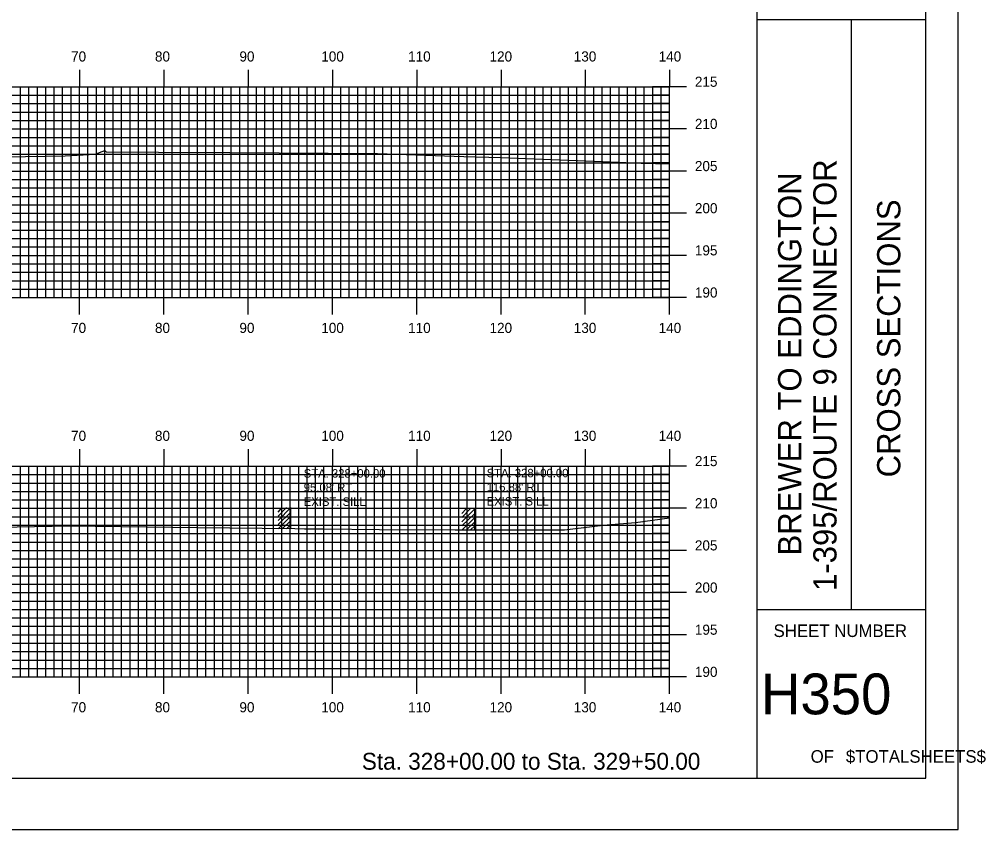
# Model space of a CAD drawing. Extents: x 1821998 to 1822342, y 442591 to 442811.
# Drawn here: x 1822227.1 to 1822341.8, y 442590.5 to 442686.7 of the extents above; entities that cross this region are included whole.
import ezdxf

# ---------------------------------------------------------------- set-up
doc = ezdxf.new("R2010")
doc.units = 0
for name, color, linetype in [('BORDER', 7, 'Continuous'), ('D_Text_Monospaced', 7, 'Continuous'), ('H_V ANNOTATION', 7, 'Continuous'), ('M_Buildings_Attachments', 7, 'Continuous'), ('MAJOR', 7, 'Continuous'), ('MINOR', 7, 'Continuous'), ('PLOT BOUNDARY', 7, 'Continuous'), ('S_Roadway_Centerline', 7, 'Continuous')]:
    doc.layers.add(name, color=color, linetype=linetype)

msp = doc.modelspace()

# ---------------------------------------------------------------- linework, layer by layer
at = {"layer": 'BORDER'}
for p, q in [((1822314.66, 442596.67), (1822314.66, 442806.67)), ((1822314.66, 442686.67), (1822334.66, 442686.67)), ((1822325.84, 442616.67), (1822325.84, 442686.67)), ((1822314.66, 442616.67), (1822334.66, 442616.67))]:
    msp.add_line(p, q, dxfattribs=at)
msp.add_lwpolyline([(1822014.66, 442596.67), (1822334.66, 442596.67), (1822334.66, 442806.67), (1822014.66, 442806.67)], close=True, dxfattribs=at)
at = {"layer": 'M_Buildings_Attachments'}
for p, q in [((1822257.83, 442627.24), (1822259.34, 442628.75)), ((1822257.83, 442627.73), (1822258.81, 442628.75)), ((1822257.83, 442628.23), (1822258.32, 442628.75)), ((1822259.34, 442626.23), (1822259.34, 442628.75)), ((1822279.63, 442627.08), (1822281.14, 442628.59)), ((1822279.63, 442627.57), (1822280.61, 442628.59)), ((1822279.63, 442628.06), (1822280.12, 442628.59)), ((1822281.14, 442626.06), (1822281.14, 442628.59)), ((1822257.83, 442626.75), (1822259.34, 442628.23)), ((1822257.83, 442626.23), (1822259.34, 442627.73)), ((1822258.32, 442626.23), (1822259.34, 442627.24)), ((1822279.63, 442626.59), (1822281.14, 442628.06)), ((1822279.63, 442626.06), (1822281.14, 442627.57)), ((1822258.81, 442626.23), (1822259.34, 442626.75)), ((1822280.12, 442626.06), (1822281.14, 442627.08)), ((1822280.61, 442626.06), (1822281.14, 442626.59))]:
    msp.add_line(p, q, dxfattribs=at)
at = {"layer": 'MAJOR'}
for p, q in [((1822234.26, 442680.67), (1822234.26, 442678.67)), ((1822244.26, 442680.67), (1822244.26, 442678.67)), ((1822254.26, 442680.67), (1822254.26, 442678.67)), ((1822264.26, 442680.67), (1822264.26, 442678.67)), ((1822274.26, 442680.67), (1822274.26, 442678.67)), ((1822284.26, 442680.67), (1822284.26, 442678.67)), ((1822294.26, 442680.67), (1822294.26, 442678.67)), ((1822304.26, 442680.67), (1822304.26, 442678.67)), ((1822024.26, 442678.67), (1822304.26, 442678.67)), ((1822024.26, 442678.67), (1822304.26, 442678.67)), ((1822234.26, 442653.67), (1822234.26, 442678.67)), ((1822244.26, 442653.67), (1822244.26, 442678.67)), ((1822254.26, 442653.67), (1822254.26, 442678.67)), ((1822264.26, 442653.67), (1822264.26, 442678.67)), ((1822274.26, 442653.67), (1822274.26, 442678.67)), ((1822284.26, 442653.67), (1822284.26, 442678.67)), ((1822294.26, 442653.67), (1822294.26, 442678.67)), ((1822306.26, 442678.67), (1822302.25, 442678.67)), ((1822304.26, 442653.67), (1822304.26, 442678.67)), ((1822304.26, 442653.67), (1822304.26, 442678.67)), ((1822024.26, 442673.67), (1822304.26, 442673.67)), ((1822306.26, 442673.67), (1822302.25, 442673.67)), ((1822024.26, 442668.67), (1822304.26, 442668.67)), ((1822306.26, 442668.67), (1822302.25, 442668.67)), ((1822024.26, 442663.67), (1822304.26, 442663.67)), ((1822306.26, 442663.67), (1822302.25, 442663.67)), ((1822024.26, 442658.67), (1822304.26, 442658.67)), ((1822306.26, 442658.67), (1822302.25, 442658.67)), ((1822024.26, 442653.67), (1822304.26, 442653.67)), ((1822024.26, 442653.67), (1822304.26, 442653.67)), ((1822234.26, 442651.66), (1822234.26, 442653.67)), ((1822244.26, 442651.66), (1822244.26, 442653.67)), ((1822254.26, 442651.66), (1822254.26, 442653.67)), ((1822264.26, 442651.66), (1822264.26, 442653.67)), ((1822274.26, 442651.66), (1822274.26, 442653.67)), ((1822284.26, 442651.66), (1822284.26, 442653.67)), ((1822294.26, 442651.66), (1822294.26, 442653.67)), ((1822306.26, 442653.67), (1822302.25, 442653.67)), ((1822304.26, 442651.66), (1822304.26, 442653.67)), ((1822234.26, 442635.67), (1822234.26, 442633.67)), ((1822244.26, 442635.67), (1822244.26, 442633.67)), ((1822254.26, 442635.67), (1822254.26, 442633.67)), ((1822264.26, 442635.67), (1822264.26, 442633.67)), ((1822274.26, 442635.67), (1822274.26, 442633.67)), ((1822284.26, 442635.67), (1822284.26, 442633.67)), ((1822294.26, 442635.67), (1822294.26, 442633.67)), ((1822304.26, 442635.67), (1822304.26, 442633.67)), ((1822024.26, 442633.67), (1822304.26, 442633.67)), ((1822024.26, 442633.67), (1822304.26, 442633.67)), ((1822234.26, 442608.67), (1822234.26, 442633.67)), ((1822244.26, 442608.67), (1822244.26, 442633.67)), ((1822254.26, 442608.67), (1822254.26, 442633.67)), ((1822264.26, 442608.67), (1822264.26, 442633.67)), ((1822274.26, 442608.67), (1822274.26, 442633.67)), ((1822284.26, 442608.67), (1822284.26, 442633.67)), ((1822294.26, 442608.67), (1822294.26, 442633.67)), ((1822306.26, 442633.67), (1822302.25, 442633.67)), ((1822304.26, 442608.67), (1822304.26, 442633.67)), ((1822304.26, 442608.67), (1822304.26, 442633.67)), ((1822024.26, 442628.67), (1822304.26, 442628.67)), ((1822306.26, 442628.67), (1822302.25, 442628.67)), ((1822024.26, 442623.67), (1822304.26, 442623.67)), ((1822306.26, 442623.67), (1822302.25, 442623.67)), ((1822024.26, 442618.67), (1822304.26, 442618.67)), ((1822306.26, 442618.67), (1822302.25, 442618.67)), ((1822024.26, 442613.67), (1822304.26, 442613.67)), ((1822306.26, 442613.67), (1822302.25, 442613.67)), ((1822024.26, 442608.67), (1822304.26, 442608.67)), ((1822024.26, 442608.67), (1822304.26, 442608.67)), ((1822234.26, 442606.66), (1822234.26, 442608.67)), ((1822244.26, 442606.66), (1822244.26, 442608.67)), ((1822254.26, 442606.66), (1822254.26, 442608.67)), ((1822264.26, 442606.66), (1822264.26, 442608.67)), ((1822274.26, 442606.66), (1822274.26, 442608.67)), ((1822284.26, 442606.66), (1822284.26, 442608.67)), ((1822294.26, 442606.66), (1822294.26, 442608.67)), ((1822306.26, 442608.67), (1822302.25, 442608.67)), ((1822304.26, 442606.66), (1822304.26, 442608.67))]:
    msp.add_line(p, q, dxfattribs=at)
at = {"layer": 'MINOR'}
for p, q in [((1822227.26, 442653.67), (1822227.26, 442678.67)), ((1822228.26, 442653.67), (1822228.26, 442678.67)), ((1822229.26, 442653.67), (1822229.26, 442678.67)), ((1822230.26, 442653.67), (1822230.26, 442678.67)), ((1822231.26, 442653.67), (1822231.26, 442678.67)), ((1822232.26, 442653.67), (1822232.26, 442678.67)), ((1822233.26, 442653.67), (1822233.26, 442678.67)), ((1822235.26, 442653.67), (1822235.26, 442678.67)), ((1822236.26, 442653.67), (1822236.26, 442678.67)), ((1822237.26, 442653.67), (1822237.26, 442678.67)), ((1822238.26, 442653.67), (1822238.26, 442678.67)), ((1822239.26, 442653.67), (1822239.26, 442678.67)), ((1822240.26, 442653.67), (1822240.26, 442678.67)), ((1822241.26, 442653.67), (1822241.26, 442678.67)), ((1822242.26, 442653.67), (1822242.26, 442678.67)), ((1822243.26, 442653.67), (1822243.26, 442678.67)), ((1822245.26, 442653.67), (1822245.26, 442678.67)), ((1822246.26, 442653.67), (1822246.26, 442678.67)), ((1822247.26, 442653.67), (1822247.26, 442678.67)), ((1822248.26, 442653.67), (1822248.26, 442678.67)), ((1822249.26, 442653.67), (1822249.26, 442678.67)), ((1822250.26, 442653.67), (1822250.26, 442678.67)), ((1822251.26, 442653.67), (1822251.26, 442678.67)), ((1822252.26, 442653.67), (1822252.26, 442678.67)), ((1822253.26, 442653.67), (1822253.26, 442678.67)), ((1822255.26, 442653.67), (1822255.26, 442678.67)), ((1822256.26, 442653.67), (1822256.26, 442678.67)), ((1822257.26, 442653.67), (1822257.26, 442678.67)), ((1822258.26, 442653.67), (1822258.26, 442678.67)), ((1822259.26, 442653.67), (1822259.26, 442678.67)), ((1822260.26, 442653.67), (1822260.26, 442678.67)), ((1822261.26, 442653.67), (1822261.26, 442678.67)), ((1822262.26, 442653.67), (1822262.26, 442678.67)), ((1822263.26, 442653.67), (1822263.26, 442678.67)), ((1822265.26, 442653.67), (1822265.26, 442678.67)), ((1822266.26, 442653.67), (1822266.26, 442678.67)), ((1822267.26, 442653.67), (1822267.26, 442678.67)), ((1822268.26, 442653.67), (1822268.26, 442678.67)), ((1822269.26, 442653.67), (1822269.26, 442678.67)), ((1822270.26, 442653.67), (1822270.26, 442678.67)), ((1822271.26, 442653.67), (1822271.26, 442678.67)), ((1822272.26, 442653.67), (1822272.26, 442678.67)), ((1822273.26, 442653.67), (1822273.26, 442678.67)), ((1822275.26, 442653.67), (1822275.26, 442678.67)), ((1822276.26, 442653.67), (1822276.26, 442678.67)), ((1822277.26, 442653.67), (1822277.26, 442678.67)), ((1822278.26, 442653.67), (1822278.26, 442678.67)), ((1822279.26, 442653.67), (1822279.26, 442678.67)), ((1822280.26, 442653.67), (1822280.26, 442678.67)), ((1822281.26, 442653.67), (1822281.26, 442678.67)), ((1822282.26, 442653.67), (1822282.26, 442678.67)), ((1822283.26, 442653.67), (1822283.26, 442678.67)), ((1822285.26, 442653.67), (1822285.26, 442678.67)), ((1822286.26, 442653.67), (1822286.26, 442678.67)), ((1822287.26, 442653.67), (1822287.26, 442678.67)), ((1822288.26, 442653.67), (1822288.26, 442678.67)), ((1822289.26, 442653.67), (1822289.26, 442678.67)), ((1822290.26, 442653.67), (1822290.26, 442678.67)), ((1822291.26, 442653.67), (1822291.26, 442678.67)), ((1822292.26, 442653.67), (1822292.26, 442678.67)), ((1822293.26, 442653.67), (1822293.26, 442678.67)), ((1822295.26, 442653.67), (1822295.26, 442678.67)), ((1822296.26, 442653.67), (1822296.26, 442678.67)), ((1822297.26, 442653.67), (1822297.26, 442678.67)), ((1822298.26, 442653.67), (1822298.26, 442678.67)), ((1822299.26, 442653.67), (1822299.26, 442678.67)), ((1822300.26, 442653.67), (1822300.26, 442678.67)), ((1822301.26, 442653.67), (1822301.26, 442678.67)), ((1822302.26, 442653.67), (1822302.26, 442678.67)), ((1822303.26, 442653.67), (1822303.26, 442678.67)), ((1822024.26, 442677.67), (1822304.26, 442677.67)), ((1822024.26, 442676.67), (1822304.26, 442676.67)), ((1822304.26, 442677.67), (1822302.25, 442677.67)), ((1822304.26, 442676.67), (1822302.25, 442676.67)), ((1822024.26, 442675.67), (1822304.26, 442675.67)), ((1822304.26, 442675.67), (1822302.25, 442675.67)), ((1822024.26, 442674.67), (1822304.26, 442674.67)), ((1822304.26, 442674.67), (1822302.25, 442674.67)), ((1822024.26, 442672.67), (1822304.26, 442672.67)), ((1822304.26, 442672.67), (1822302.25, 442672.67)), ((1822024.26, 442671.67), (1822304.26, 442671.67)), ((1822304.26, 442671.67), (1822302.25, 442671.67)), ((1822024.26, 442670.67), (1822304.26, 442670.67)), ((1822024.26, 442669.67), (1822304.26, 442669.67)), ((1822304.26, 442670.67), (1822302.25, 442670.67)), ((1822304.26, 442669.67), (1822302.25, 442669.67)), ((1822024.26, 442667.67), (1822304.26, 442667.67)), ((1822304.26, 442667.67), (1822302.25, 442667.67)), ((1822024.26, 442666.67), (1822304.26, 442666.67)), ((1822304.26, 442666.67), (1822302.25, 442666.67)), ((1822024.26, 442665.67), (1822304.26, 442665.67)), ((1822304.26, 442665.67), (1822302.25, 442665.67)), ((1822024.26, 442664.67), (1822304.26, 442664.67)), ((1822304.26, 442664.67), (1822302.25, 442664.67)), ((1822024.26, 442662.67), (1822304.26, 442662.67)), ((1822024.26, 442661.67), (1822304.26, 442661.67)), ((1822304.26, 442662.67), (1822302.25, 442662.67)), ((1822304.26, 442661.67), (1822302.25, 442661.67)), ((1822024.26, 442660.67), (1822304.26, 442660.67)), ((1822304.26, 442660.67), (1822302.25, 442660.67)), ((1822024.26, 442659.67), (1822304.26, 442659.67)), ((1822304.26, 442659.67), (1822302.25, 442659.67)), ((1822024.26, 442657.67), (1822304.26, 442657.67)), ((1822304.26, 442657.67), (1822302.25, 442657.67)), ((1822024.26, 442656.67), (1822304.26, 442656.67)), ((1822304.26, 442656.67), (1822302.25, 442656.67)), ((1822024.26, 442655.67), (1822304.26, 442655.67)), ((1822304.26, 442655.67), (1822302.25, 442655.67)), ((1822024.26, 442654.67), (1822304.26, 442654.67)), ((1822304.26, 442654.67), (1822302.25, 442654.67)), ((1822227.26, 442608.67), (1822227.26, 442633.67)), ((1822228.26, 442608.67), (1822228.26, 442633.67)), ((1822229.26, 442608.67), (1822229.26, 442633.67)), ((1822230.26, 442608.67), (1822230.26, 442633.67)), ((1822231.26, 442608.67), (1822231.26, 442633.67)), ((1822232.26, 442608.67), (1822232.26, 442633.67)), ((1822233.26, 442608.67), (1822233.26, 442633.67)), ((1822235.26, 442608.67), (1822235.26, 442633.67)), ((1822236.26, 442608.67), (1822236.26, 442633.67)), ((1822237.26, 442608.67), (1822237.26, 442633.67)), ((1822238.26, 442608.67), (1822238.26, 442633.67)), ((1822239.26, 442608.67), (1822239.26, 442633.67)), ((1822240.26, 442608.67), (1822240.26, 442633.67)), ((1822241.26, 442608.67), (1822241.26, 442633.67)), ((1822242.26, 442608.67), (1822242.26, 442633.67)), ((1822243.26, 442608.67), (1822243.26, 442633.67)), ((1822245.26, 442608.67), (1822245.26, 442633.67)), ((1822246.26, 442608.67), (1822246.26, 442633.67)), ((1822247.26, 442608.67), (1822247.26, 442633.67)), ((1822248.26, 442608.67), (1822248.26, 442633.67)), ((1822249.26, 442608.67), (1822249.26, 442633.67)), ((1822250.26, 442608.67), (1822250.26, 442633.67)), ((1822251.26, 442608.67), (1822251.26, 442633.67)), ((1822252.26, 442608.67), (1822252.26, 442633.67)), ((1822253.26, 442608.67), (1822253.26, 442633.67)), ((1822255.26, 442608.67), (1822255.26, 442633.67)), ((1822256.26, 442608.67), (1822256.26, 442633.67)), ((1822257.26, 442608.67), (1822257.26, 442633.67)), ((1822258.26, 442608.67), (1822258.26, 442633.67)), ((1822259.26, 442608.67), (1822259.26, 442633.67)), ((1822260.26, 442608.67), (1822260.26, 442633.67)), ((1822261.26, 442608.67), (1822261.26, 442633.67)), ((1822262.26, 442608.67), (1822262.26, 442633.67)), ((1822263.26, 442608.67), (1822263.26, 442633.67)), ((1822265.26, 442608.67), (1822265.26, 442633.67)), ((1822266.26, 442608.67), (1822266.26, 442633.67)), ((1822267.26, 442608.67), (1822267.26, 442633.67)), ((1822268.26, 442608.67), (1822268.26, 442633.67)), ((1822269.26, 442608.67), (1822269.26, 442633.67)), ((1822270.26, 442608.67), (1822270.26, 442633.67)), ((1822271.26, 442608.67), (1822271.26, 442633.67)), ((1822272.26, 442608.67), (1822272.26, 442633.67)), ((1822273.26, 442608.67), (1822273.26, 442633.67)), ((1822275.26, 442608.67), (1822275.26, 442633.67)), ((1822276.26, 442608.67), (1822276.26, 442633.67)), ((1822277.26, 442608.67), (1822277.26, 442633.67)), ((1822278.26, 442608.67), (1822278.26, 442633.67)), ((1822279.26, 442608.67), (1822279.26, 442633.67)), ((1822280.26, 442608.67), (1822280.26, 442633.67)), ((1822281.26, 442608.67), (1822281.26, 442633.67)), ((1822282.26, 442608.67), (1822282.26, 442633.67)), ((1822283.26, 442608.67), (1822283.26, 442633.67)), ((1822285.26, 442608.67), (1822285.26, 442633.67)), ((1822286.26, 442608.67), (1822286.26, 442633.67)), ((1822287.26, 442608.67), (1822287.26, 442633.67)), ((1822288.26, 442608.67), (1822288.26, 442633.67)), ((1822289.26, 442608.67), (1822289.26, 442633.67)), ((1822290.26, 442608.67), (1822290.26, 442633.67)), ((1822291.26, 442608.67), (1822291.26, 442633.67)), ((1822292.26, 442608.67), (1822292.26, 442633.67)), ((1822293.26, 442608.67), (1822293.26, 442633.67)), ((1822295.26, 442608.67), (1822295.26, 442633.67)), ((1822296.26, 442608.67), (1822296.26, 442633.67)), ((1822297.26, 442608.67), (1822297.26, 442633.67)), ((1822298.26, 442608.67), (1822298.26, 442633.67)), ((1822299.26, 442608.67), (1822299.26, 442633.67)), ((1822300.26, 442608.67), (1822300.26, 442633.67)), ((1822301.26, 442608.67), (1822301.26, 442633.67)), ((1822302.26, 442608.67), (1822302.26, 442633.67)), ((1822303.26, 442608.67), (1822303.26, 442633.67)), ((1822024.26, 442632.67), (1822304.26, 442632.67)), ((1822304.26, 442632.67), (1822302.25, 442632.67)), ((1822024.26, 442631.67), (1822304.26, 442631.67)), ((1822304.26, 442631.67), (1822302.25, 442631.67)), ((1822024.26, 442630.67), (1822304.26, 442630.67)), ((1822024.26, 442629.67), (1822304.26, 442629.67)), ((1822304.26, 442630.67), (1822302.25, 442630.67)), ((1822304.26, 442629.67), (1822302.25, 442629.67)), ((1822024.26, 442627.67), (1822304.26, 442627.67)), ((1822304.26, 442627.67), (1822302.25, 442627.67)), ((1822024.26, 442626.67), (1822304.26, 442626.67)), ((1822304.26, 442626.67), (1822302.25, 442626.67)), ((1822024.26, 442625.67), (1822304.26, 442625.67)), ((1822304.26, 442625.67), (1822302.25, 442625.67)), ((1822024.26, 442624.67), (1822304.26, 442624.67)), ((1822304.26, 442624.67), (1822302.25, 442624.67)), ((1822024.26, 442622.67), (1822304.26, 442622.67)), ((1822304.26, 442622.67), (1822302.25, 442622.67)), ((1822024.26, 442621.67), (1822304.26, 442621.67)), ((1822304.26, 442621.67), (1822302.25, 442621.67)), ((1822024.26, 442620.67), (1822304.26, 442620.67)), ((1822304.26, 442620.67), (1822302.25, 442620.67)), ((1822024.26, 442619.67), (1822304.26, 442619.67)), ((1822304.26, 442619.67), (1822302.25, 442619.67)), ((1822024.26, 442617.67), (1822304.26, 442617.67)), ((1822304.26, 442617.67), (1822302.25, 442617.67)), ((1822024.26, 442616.67), (1822304.26, 442616.67)), ((1822304.26, 442616.67), (1822302.25, 442616.67)), ((1822024.26, 442615.67), (1822304.26, 442615.67)), ((1822024.26, 442614.67), (1822304.26, 442614.67)), ((1822304.26, 442615.67), (1822302.25, 442615.67)), ((1822304.26, 442614.67), (1822302.25, 442614.67)), ((1822024.26, 442612.67), (1822304.26, 442612.67)), ((1822304.26, 442612.67), (1822302.25, 442612.67)), ((1822024.26, 442611.67), (1822304.26, 442611.67)), ((1822304.26, 442611.67), (1822302.25, 442611.67)), ((1822024.26, 442610.67), (1822304.26, 442610.67)), ((1822304.26, 442610.67), (1822302.25, 442610.67)), ((1822024.26, 442609.67), (1822304.26, 442609.67)), ((1822304.26, 442609.67), (1822302.25, 442609.67))]:
    msp.add_line(p, q, dxfattribs=at)
at = {"layer": 'PLOT BOUNDARY'}
msp.add_lwpolyline([(1821998.47, 442590.55), (1822338.47, 442590.55), (1822338.47, 442810.55), (1821998.47, 442810.55)], close=True, dxfattribs=at)
at = {"layer": 'S_Roadway_Centerline'}
for points in [[(1822217.36, 442670.36), (1822227.86, 442670.42), (1822232.55, 442670.49), (1822236.13, 442670.69), (1822237.25, 442671.1), (1822237.43, 442670.97), (1822243.64, 442670.91), (1822252.09, 442670.88), (1822269.61, 442670.75), (1822279.84, 442670.39), (1822284.28, 442670.27), (1822296.32, 442669.79), (1822300.9, 442669.6), (1822304.26, 442669.54)], [(1822199.65, 442625.97), (1822233.12, 442626.58), (1822248.21, 442626.4), (1822259.79, 442626.26), (1822260.95, 442626.24), (1822261.8, 442626.23), (1822263.23, 442626.25), (1822269.83, 442626.17), (1822278.81, 442626.11), (1822281.14, 442626.13), (1822281.2, 442626.13), (1822281.25, 442626.13), (1822291.78, 442626.11), (1822296.36, 442626.67), (1822300.2, 442626.97), (1822304.26, 442627.53)]]:
    msp.add_lwpolyline(points, dxfattribs=at)

# ---------------------------------------------------------------- texts
at = {"layer": 'BORDER'}
for s, p in [('1-395/ROUTE 9 CONNECTOR', (1822324.06, 442618.87)), ('BREWER TO EDDINGTON', (1822319.88, 442623.07)), ('CROSS SECTIONS', (1822331.63, 442632.34))]:
    msp.add_text(s, height=2.7557, rotation=90, dxfattribs=at).set_placement(p)
for s, height, p in [('SHEET NUMBER', 1.4905, (1822316.59, 442613.4)), ('H350', 4.839, (1822315.1, 442604.23)), ('OF', 1.491, (1822320.99, 442598.49)), ('$TOTALSHEETS$', 1.4905, (1822325.17, 442598.49))]:
    msp.add_text(s, height=height, dxfattribs=at).set_placement(p)
at = {"layer": 'D_Text_Monospaced'}
for s, p in [('STA. 328+00.00', (1822260.86, 442632.31)), ('STA. 328+00.00', (1822282.56, 442632.35)), ("95.08' RT.", (1822260.86, 442630.64)), ("116.88' RT.", (1822282.56, 442630.68)), ('EXIST. SILL', (1822260.86, 442628.96)), ('EXIST. SILL', (1822282.56, 442629))]:
    msp.add_text(s, height=1, dxfattribs=at).set_placement(p)
at = {"layer": 'H_V ANNOTATION'}
for s, height, p in [('70', 1.2, (1822233.26, 442681.67)), ('80', 1.2, (1822243.21, 442681.67)), ('90', 1.2, (1822253.23, 442681.67)), ('100', 1.2, (1822262.94, 442681.67)), ('110', 1.2, (1822273.24, 442681.67)), ('120', 1.2, (1822282.9, 442681.67)), ('130', 1.2, (1822292.89, 442681.67)), ('140', 1.2, (1822302.96, 442681.67)), ('215', 1.2, (1822307.26, 442678.67)), ('210', 1.2, (1822307.26, 442673.67)), ('205', 1.2, (1822307.26, 442668.67)), ('200', 1.2, (1822307.26, 442663.67)), ('195', 1.2, (1822307.26, 442658.67)), ('190', 1.2, (1822307.26, 442653.67)), ('70', 1.2, (1822233.26, 442649.47)), ('80', 1.2, (1822243.21, 442649.47)), ('90', 1.2, (1822253.23, 442649.47)), ('100', 1.2, (1822262.94, 442649.47)), ('110', 1.2, (1822273.24, 442649.47)), ('120', 1.2, (1822282.9, 442649.47)), ('130', 1.2, (1822292.89, 442649.47)), ('140', 1.2, (1822302.96, 442649.47)), ('70', 1.2, (1822233.26, 442636.67)), ('80', 1.2, (1822243.21, 442636.67)), ('90', 1.2, (1822253.23, 442636.67)), ('100', 1.2, (1822262.94, 442636.67)), ('110', 1.2, (1822273.24, 442636.67)), ('120', 1.2, (1822282.9, 442636.67)), ('130', 1.2, (1822292.89, 442636.67)), ('140', 1.2, (1822302.96, 442636.67)), ('215', 1.2, (1822307.26, 442633.67)), ('210', 1.2, (1822307.26, 442628.67)), ('205', 1.2, (1822307.26, 442623.67)), ('200', 1.2, (1822307.26, 442618.67)), ('195', 1.2, (1822307.26, 442613.67)), ('190', 1.2, (1822307.26, 442608.67)), ('70', 1.2, (1822233.26, 442604.47)), ('80', 1.2, (1822243.21, 442604.47)), ('90', 1.2, (1822253.23, 442604.47)), ('100', 1.2, (1822262.94, 442604.47)), ('110', 1.2, (1822273.24, 442604.47)), ('120', 1.2, (1822282.9, 442604.47)), ('130', 1.2, (1822292.89, 442604.47)), ('140', 1.2, (1822302.96, 442604.47)), ('Sta. 328+00.00 to Sta. 329+50.00', 2.0004, (1822267.75, 442597.66))]:
    msp.add_text(s, height=height, dxfattribs=at).set_placement(p)

doc.saveas('drawing.dxf')
